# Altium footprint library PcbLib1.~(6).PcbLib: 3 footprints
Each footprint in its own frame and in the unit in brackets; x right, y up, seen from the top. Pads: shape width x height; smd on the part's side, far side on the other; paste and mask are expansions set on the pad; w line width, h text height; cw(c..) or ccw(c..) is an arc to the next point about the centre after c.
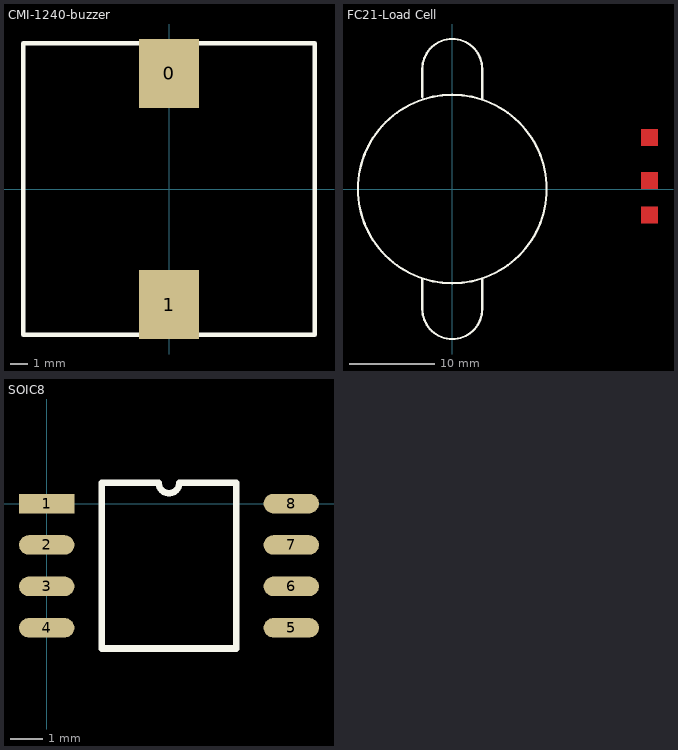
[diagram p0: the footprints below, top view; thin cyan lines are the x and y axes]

## CMI-1240-buzzer [mm]
pads (2):
  rect 3.5x4 smd: 0(0,6.7) 1(0,-6.7)
Top Overlay:
  lines w0.254: -8.45,-8.45 -8.45,8.45 8.45,8.45 8.45,-8.45 -8.45,-8.45

## FC21-Load Cell [mm]
Top Layer:
  rectangle: 22,-4.017 24,-2.017
  rectangle: 22,5 24,7
  rectangle: 22,0 24,2
Top Overlay:
  circle w0.254: c0,0 r11
  lines w0.254: -3.5,-10.47 -3.5,-14 ccw(c0,-14) 3.5,-14 3.5,-10.485 ; -3.5,10.724 -3.5,14 cw(c0,14) 3.5,14 3.5,10.485

## SOIC8 [mm]
pads (8):
  rect 1.7x0.6 smd: 1(0,0)
  oval 1.7x0.6 smd: 2(0,-1.27) 3(0,-2.54) 4(0,-3.81) 5(7.5,-3.81) 6(7.5,-2.54) 7(7.5,-1.27) 8(7.5,0)
Top Overlay:
  lines w0.2: 1.685,-4.445 5.815,-4.445 5.815,0.635 4.068,0.635 cw(c3.75,0.635) 3.433,0.635 1.685,0.635 1.685,-4.445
